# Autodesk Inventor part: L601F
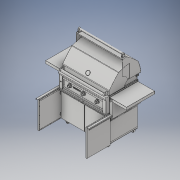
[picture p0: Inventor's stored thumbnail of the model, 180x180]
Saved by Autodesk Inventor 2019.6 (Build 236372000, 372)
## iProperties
Created: 2025-04
Part Number: L601F
Material: Generic
Description: CATIA V5 STEP
Document SubType Name: Modeling
Designer: MMAK
Authority: none
Density: 1 g/cm^3
Appearance: Default
Company: none
Title: C:\Users\MMAK\Documents\SmarTeam\WEBSITE CAD\SEDONA\2025 SEDONA\L601F.stp
Author: none
Revision Number: ANY
Sending System: CATIA V5 STEP AP203 v2
Preprocessor: CATIA Unofficial Packaging Version SP2
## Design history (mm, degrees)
feature "81699-1_81679-1_81678-1_37889-1-solid1"
feature "81699-1_81679-1_81678-1_32769-1-solid1"
feature "81699-1_81679-1_81678-1_32769-2-solid1"
feature "81699-1_81679-1_81678-1_32218--1-solid1"
feature "81699-1_81679-1_81678-1_32218--2-solid1"
feature "81699-1_81679-1_81534-2_37528-2-solid1"
feature "81699-1_81679-1_81534-2_32769-1-solid1"
feature "81699-1_81679-1_81534-2_32769-2-solid1"
feature "81699-1_81679-1_81534-2_32218-14-solid1"
feature "81699-1_81679-1_81534-2_37165-1-solid1"
feature "81699-1_81679-1_81676-2_37886-1-solid1"
feature "81699-1_81679-1_81676-2_32769-1-solid1"
feature "81699-1_81679-1_81676-2_32769-2-solid1"
feature "81699-1_81679-1_81676-2_37165-11-solid1"
feature "81699-1_81679-1_81677-1_37887-1-solid1"
feature "81699-1_81679-1_81677-1_37901-1-solid1"
feature "81699-1_81679-1_81677-1_32769-1-solid1"
feature "81699-1_81679-1_81677-1_32769-2-solid1"
feature "81699-1_81679-1_81677-1_32769-3-solid1"
feature "81699-1_81679-1_81677-1_32769-4-solid1"
feature "81699-1_81679-1_81677-1_32769-5-solid1"
feature "81699-1_81679-1_81677-1_32769-6-solid1"
feature "81699-1_81679-1_81677-1_32769-7-solid1"
feature "81699-1_81679-1_81677-1_32769-8-solid1"
feature "81699-1_81679-1_81677-1_32769-9-solid1"
feature "81699-1_81679-1_81677-1_32769-10-solid1"
feature "81699-1_81679-1_81677-1_32769-11-solid1"
feature "81699-1_81679-1_81677-1_32769-12-solid1"
feature "81699-1_81679-1_81677-1_32769-21-solid1"
feature "81699-1_81679-1_81677-1_32769-25-solid1"
feature "81699-1_81679-1_81677-1_32769-26-solid1"
feature "81699-1_81679-1_81677-1_32769-27-solid1"
feature "81699-1_81679-1_30662-1-solid1"
feature "81699-1_81679-1_30662-1-solid2"
feature "81699-1_81679-1_30662-1-solid3"
feature "81699-1_81679-1_30662-2-solid1"
feature "81699-1_81679-1_30662-2-solid2"
feature "81699-1_81679-1_30662-2-solid3"
feature "81699-1_81679-1_33843-1-solid1"
feature "81699-1_81679-1_33843-1-solid2"
feature "81699-1_81679-1_33843-2-solid1"
feature "81699-1_81679-1_33843-2-solid2"
feature "81699-1_81679-1_37167-1-solid1"
feature "81699-1_81679-1_37167-17-solid1"
feature "81699-1_81679-1_37167-18-solid1"
feature "81699-1_81679-1_37167-19-solid1"
feature "81699-1_81679-1_37167-21-solid1"
feature "81699-1_81679-1_37167-24-solid1"
feature "81699-1_81679-1_37167-26-solid1"
feature "81699-1_81679-1_37167-28-solid1"
feature "81699-1_81679-1_37167-30-solid1"
feature "81699-1_81679-1_37167-32-solid1"
feature "81699-1_81679-1_37167-34-solid1"
feature "81699-1_81679-1_37167-36-solid1"
feature "81699-1_81679-1_37167-38-solid1"
feature "81699-1_81679-1_37167-40-solid1"
feature "81699-1_81679-1_37167-42-solid1"
feature "81699-1_81679-1_37167-44-solid1"
feature "81699-1_81404-3_37070-1-solid1"
feature "81699-1_81404-3_32769-1-solid1"
feature "81699-1_81404-3_32769-2-solid1"
feature "81699-1_81404-3_32769-4-solid1"
feature "81699-1_81404-3_32769-6-solid1"
feature "81699-1_37888-1-solid1"
feature "81699-1_37907-2-solid1"
feature "81699-1_37168-1-solid1"
feature "81699-1_37168-4-solid1"
feature "81699-1_70696-2_37100-1-solid1"
feature "81699-1_70696-2_34888-1-solid1"
feature "81699-1_70696-2_31643-1-solid1"
feature "81699-1_70696-2_31643-3-solid1"
feature "81699-1_70696-1_37100-1-solid1"
feature "81699-1_70696-1_34888-1-solid1"
feature "81699-1_70696-1_31643-1-solid1"
feature "81699-1_70696-1_31643-3-solid1"
feature "81699-1_70696-3_37100-1-solid1"
feature "81699-1_70696-3_31643-2-solid1"
feature "81699-1_70696-3_34888-3-solid1"
feature "81699-1_70696-3_31643-4-solid1"
feature "81699-1_70696-4_37100-1-solid1"
feature "81699-1_70696-4_31643-2-solid1"
feature "81699-1_70696-4_34888-3-solid1"
feature "81699-1_70696-4_31643-4-solid1"
feature "81699-1_31876-10-solid1"
feature "81699-1_31876-1-solid1"
feature "81699-1_31876-2-solid1"
feature "81699-1_31876-5-solid1"
feature "81699-1_31876-11-solid1"
feature "81699-1_31876-12-solid1"
feature "81699-1_37167-47-solid1"
feature "81699-1_37167-45-solid1"
feature "81699-1_37167-48-solid1"
feature "81699-1_37167-46-solid1"
feature "81699-1_37167-41-solid1"
feature "81699-1_37167-43-solid1"
feature "81699-1_37167-49-solid1"
feature "81699-1_37167-50-solid1"
feature "81699-1_37165-3-solid1"
feature "81699-1_37165-2-solid1"
feature "81699-1_30292-1-solid1"
feature "81699-1_30292-2-solid1"
feature "81699-1_30292-4-solid1"
feature "81699-1_30292-6-solid1"
feature "81699-1_30292-7-solid1"
feature "81699-1_81530-1_37102-1-solid1"
feature "81699-1_81530-1_31205-1-solid1"
feature "81699-1_81530-1_31206-5-solid1"
feature "81699-1_81530-1_31206-6-solid1"
feature "81699-1_81530-1_31206-4-solid1"
feature "81699-1_81530-1_31206-7-solid1"
feature "81699-1_37166-2-solid1"
feature "81699-1_37166-1-solid1"
feature "81699-1_37166-3-solid1"
feature "81699-1_37166-4-solid1"
feature "81699-1_37166-6-solid1"
feature "81699-1_37166-10-solid1"
feature "81699-1_37166-12-solid1"
feature "81699-1_37166-15-solid1"
feature "81699-1_81698-1_81703-1_37540-1-solid1"
feature "81699-1_81698-1_81703-1_37797-1-solid1"
feature "81699-1_81698-1_81703-1_37978-1-solid1"
feature "81699-1_81698-1_81703-1_30292-1-solid1"
feature "81699-1_81698-1_81703-1_30292-2-solid1"
feature "81699-1_81698-1_81703-1_30292-3-solid1"
feature "81699-1_81698-1_81703-1_30292-5-solid1"
feature "81699-1_81698-1_81703-1_30292-6-solid1"
feature "81699-1_81698-1_81703-1_30292-7-solid1"
feature "81699-1_81698-1_81703-1_30292-8-solid1"
feature "81699-1_81698-1_81703-1_30292-9-solid1"
feature "81699-1_81698-1_81703-1_30292-10-solid1"
feature "81699-1_81698-1_81703-1_30292-11-solid1"
feature "81699-1_81698-1_81703-1_30292-12-solid1"
feature "81699-1_81698-1_81703-1_30292-13-solid1"
feature "81699-1_81698-1_81703-1_30292-14-solid1"
feature "81699-1_81698-1_81703-1_30292-16-solid1"
feature "81699-1_81698-1_81703-1_30292-18-solid1"
feature "81699-1_81698-1_81703-1_30292-20-solid1"
feature "81699-1_81698-1_81703-1_30292-22-solid1"
feature "81699-1_81698-1_32218--1-solid1"
feature "81699-1_81698-1_32218--2-solid1"
feature "81699-1_81698-1_32218--3-solid1"
feature "81699-1_81698-1_32218--4-solid1"
feature "81699-1_81698-2_81703-1_37540-1-solid1"
feature "81699-1_81698-2_81703-1_37797-1-solid1"
feature "81699-1_81698-2_81703-1_37978-1-solid1"
feature "81699-1_81698-2_81703-1_30292-1-solid1"
feature "81699-1_81698-2_81703-1_30292-2-solid1"
feature "81699-1_81698-2_81703-1_30292-3-solid1"
feature "81699-1_81698-2_81703-1_30292-5-solid1"
feature "81699-1_81698-2_81703-1_30292-6-solid1"
feature "81699-1_81698-2_81703-1_30292-7-solid1"
feature "81699-1_81698-2_81703-1_30292-8-solid1"
feature "81699-1_81698-2_81703-1_30292-9-solid1"
feature "81699-1_81698-2_81703-1_30292-10-solid1"
feature "81699-1_81698-2_81703-1_30292-11-solid1"
feature "81699-1_81698-2_81703-1_30292-12-solid1"
feature "81699-1_81698-2_81703-1_30292-13-solid1"
feature "81699-1_81698-2_81703-1_30292-14-solid1"
feature "81699-1_81698-2_81703-1_30292-16-solid1"
feature "81699-1_81698-2_81703-1_30292-18-solid1"
feature "81699-1_81698-2_81703-1_30292-20-solid1"
feature "81699-1_81698-2_81703-1_30292-22-solid1"
feature "81699-1_81698-2_32218--1-solid1"
feature "81699-1_81698-2_32218--2-solid1"
feature "81699-1_81698-2_32218--3-solid1"
feature "81699-1_81698-2_32218--4-solid1"
feature "81699-1_81697-2_81702-1_37540-1-solid1"
feature "81699-1_81697-2_81702-1_37549-1-solid1"
feature "81699-1_81697-2_81702-1_37978-1-solid1"
feature "81699-1_81697-2_81702-1_30292-1-solid1"
feature "81699-1_81697-2_81702-1_30292-2-solid1"
feature "81699-1_81697-2_81702-1_30292-3-solid1"
feature "81699-1_81697-2_81702-1_30292-4-solid1"
feature "81699-1_81697-2_81702-1_30292-5-solid1"
feature "81699-1_81697-2_81702-1_30292-6-solid1"
feature "81699-1_81697-2_81702-1_30292-7-solid1"
feature "81699-1_81697-2_81702-1_30292-8-solid1"
feature "81699-1_81697-2_81702-1_30292-9-solid1"
feature "81699-1_81697-2_81702-1_30292-10-solid1"
feature "81699-1_81697-2_81702-1_30292-11-solid1"
feature "81699-1_81697-2_81702-1_30292-12-solid1"
feature "81699-1_81697-2_81702-1_30292-13-solid1"
feature "81699-1_81697-2_81702-1_30292-15-solid1"
feature "81699-1_81697-2_81702-1_30292-17-solid1"
feature "81699-1_81697-2_81702-1_30292-19-solid1"
feature "81699-1_81697-2_81702-1_30292-21-solid1"
feature "81699-1_81697-2_32218--1-solid1"
feature "81699-1_81697-2_32218--2-solid1"
feature "81699-1_81697-2_32218--3-solid1"
feature "81699-1_81697-2_32218--4-solid1"
feature "81699-1_81697-3_81702-1_37540-1-solid1"
feature "81699-1_81697-3_81702-1_37549-1-solid1"
feature "81699-1_81697-3_81702-1_37978-1-solid1"
feature "81699-1_81697-3_81702-1_30292-1-solid1"
feature "81699-1_81697-3_81702-1_30292-2-solid1"
feature "81699-1_81697-3_81702-1_30292-3-solid1"
feature "81699-1_81697-3_81702-1_30292-4-solid1"
feature "81699-1_81697-3_81702-1_30292-5-solid1"
feature "81699-1_81697-3_81702-1_30292-6-solid1"
feature "81699-1_81697-3_81702-1_30292-7-solid1"
feature "81699-1_81697-3_81702-1_30292-8-solid1"
feature "81699-1_81697-3_81702-1_30292-9-solid1"
feature "81699-1_81697-3_81702-1_30292-10-solid1"
feature "81699-1_81697-3_81702-1_30292-11-solid1"
feature "81699-1_81697-3_81702-1_30292-12-solid1"
feature "81699-1_81697-3_81702-1_30292-13-solid1"
feature "81699-1_81697-3_81702-1_30292-15-solid1"
feature "81699-1_81697-3_81702-1_30292-17-solid1"
feature "81699-1_81697-3_81702-1_30292-19-solid1"
feature "81699-1_81697-3_81702-1_30292-21-solid1"
feature "81699-1_81697-3_32218--1-solid1"
feature "81699-1_81697-3_32218--2-solid1"
feature "81699-1_81697-3_32218--3-solid1"
feature "81699-1_81697-3_32218--4-solid1"
feature "81699-1_37795-3-solid1"
feature "81699-1_37795-2-solid1"
feature "81699-1_37795-4-solid1"
feature "81699-1_37795-5-solid1"
feature "L601-1_10001-2-solid1"
feature "L601-1_10001-3-solid1"
feature "L601-1_10001-4-solid1"
feature "L601-1_11117-1-solid1"
feature "L601-1_11117-2-solid1"
feature "L601-1_11117-3-solid1"
feature "L601-1_11117-4-solid1"
feature "L601-1_14012-1-solid1"
feature "L601-1_14012-2-solid1"
feature "L601-1_14012-4-solid1"
feature "L601-1_14012-5-solid1"
feature "L601-1_14012-6-solid1"
feature "L601-1_14012-7-solid1"
feature "L601-1_14012-8-solid1"
feature "L601-1_14012-9-solid1"
feature "L601-1_14012-10-solid1"
feature "L601-1_14012-11-solid1"
feature "L601-1_14012-12-solid1"
feature "L601-1_14012-14-solid1"
feature "L601-1_14013-1-solid1"
feature "L601-1_14013-2-solid1"
feature "L601-1_81632-1_34062-1-solid1"
feature "L601-1_81632-1_33767-1-solid1"
feature "L601-1_81632-1_33768-1-solid1"
feature "L601-1_81632-3_34062-1-solid1"
feature "L601-1_81632-3_33767-1-solid1"
feature "L601-1_81632-3_33768-1-solid1"
feature "L601-1_81692-1_81627-1_37834-2-solid1"
feature "L601-1_81692-1_81627-1_32769-1-solid1"
feature "L601-1_81692-1_81627-1_32769-2-solid1"
feature "L601-1_81692-1_81627-1_32769-3-solid1"
feature "L601-1_81692-1_81627-1_32769-4-solid1"
feature "L601-1_81692-1_81627-1_32769-5-solid1"
feature "L601-1_81692-1_81627-1_31782-1-solid1"
feature "L601-1_81692-1_81627-1_32218-3-solid1"
feature "L601-1_81692-1_81627-1_32218-4-solid1"
feature "L601-1_81692-1_81628-1_37837-2-solid1"
feature "L601-1_81692-1_81628-1_32218-3-solid1"
feature "L601-1_81692-1_81628-1_32218-4-solid1"
feature "L601-1_81692-1_81628-1_31782-1-solid1"
feature "L601-1_81692-1_81628-1_32769-1-solid1"
feature "L601-1_81692-1_81628-1_32769-2-solid1"
feature "L601-1_81692-1_81628-1_32769-3-solid1"
feature "L601-1_81692-1_81628-1_32769-4-solid1"
feature "L601-1_81692-1_14012-1-solid1"
feature "L601-1_81692-1_14012-2-solid1"
feature "L601-1_81692-1_14012-4-solid1"
feature "L601-1_81692-1_14012-6-solid1"
feature "L601-1_81692-1_14012-8-solid1"
feature "L601-1_81692-1_14012-10-solid1"
feature "L601-1_81692-1_14012-12-solid1"
feature "L601-1_81692-1_14012-15-solid1"
feature "L601-1_81692-1_14024-1-solid1"
feature "L601-1_81692-1_14024-1-solid2"
feature "L601-1_81692-1_14024-2-solid1"
feature "L601-1_81692-1_14024-2-solid2"
feature "L601-1_81692-1_70790-1_37801-2-solid1"
feature "L601-1_81692-1_70790-1_14011-1-solid1"
feature "L601-1_81700-1_70793-1_L18041-1-solid1"
feature "L601-1_81700-1_70793-1_33763-1-solid1"
feature "L601-1_81700-1_70793-1_37975-1-solid1"
feature "L601-1_81700-1_32218-1-solid1"
feature "L601-1_81700-1_32218-2-solid1"
feature "L601-1_80733-1_80702-1_34073-1-solid1"
feature "L601-1_80733-1_80702-1_34073-1-solid2"
feature "L601-1_80733-1_80702-1_10041-1-solid1"
feature "L601-1_80733-1_80702-1_10041-2-solid1"
feature "L601-1_80733-1_13029-1-solid1"
feature "L601-1_80733-1_34267-1-solid1"
feature "L601-1_80733-1_34268-1-solid1"
feature "L601-1_80733-1_13024-1-solid1"
feature "NONE"
feature "NONE:1"
feature "NONE:2"
feature "L601-1_80733-1_13024-2-solid1"
feature "L601-1_32469-1-solid1"
feature "L601-1_32469-3-solid1"
feature "L601-1_32469-2-solid1"
feature "L601-1_32469-4-solid1"
feature "L601-1_32477-1-solid1"
feature "L601-1_32477-2-solid1"
feature "L601-1_32554-1-solid1"
feature "L601-1_32554-1-solid2"
feature "L601-1_32554-2-solid1"
feature "L601-1_32554-2-solid2"
feature "L601-1_32554-3-solid1"
feature "L601-1_32554-3-solid2"
feature "L601-1_33558-1-solid1"
feature "L601-1_37979-2-solid1"
feature "L601-1_37980-1-solid1"
feature "L601-1_38061-2-solid1"
feature "L601-1_34075-1-solid1"
feature "L601-1_34075-2-solid1"
feature "L601-1_34106-1-solid1"
feature "L601-1_36967-1-solid1"
feature "L601-1_36967-2-solid1"
feature "L601-1_80696-1_34055-1-solid1"
feature "L601-1_80696-1_34053-1-solid1"
feature "L601-1_80696-1_34054-1-solid1"
feature "L601-1_80696-1_14011-25-solid1"
feature "L601-1_80696-1_14011-27-solid1"
feature "L601-1_80696-1_14011-29-solid1"
feature "L601-1_80696-1_14011-30-solid1"
feature "L601-1_80696-1_14011-32-solid1"
feature "L601-1_80696-1_14011-34-solid1"
feature "L601-1_80696-1_30292-1-solid1"
feature "L601-1_80696-1_30292-3-solid1"
feature "L601-1_80696-1_31643-25-solid1"
feature "L601-1_80696-1_31643-53-solid1"
feature "L601-1_80696-1_30616-27-solid1"
feature "L601-1_80696-1_30616-29-solid1"
feature "L601-1_80696-1_30616-31-solid1"
feature "L601-1_80696-1_30616-44-solid1"
feature "L601-1_80696-1_30616-45-solid1"
feature "L601-1_80696-1_30616-46-solid1"
feature "L601-1_80696-1_30616-48-solid1"
feature "L601-1_80696-1_30616-49-solid1"
feature "L601-1_80696-1_30616-51-solid1"
feature "L601-1_80696-1_30616-52-solid1"
feature "L601-1_80696-1_30616-54-solid1"
feature "L601-1_80696-1_30616-55-solid1"
feature "L601-1_80696-1_14034-3-solid1"
feature "L601-1_80696-1_33758-1-solid1"
feature "L601-1_80696-1_33759-1-solid1"
feature "L601-1_80696-1_34056-1-solid1"
feature "L601-1_80696-1_14011-35-solid1"
feature "L601-1_80696-1_14011-36-solid1"
feature "L601-1_80696-1_14011-38-solid1"
feature "L601-1_80696-1_14011-40-solid1"
feature "L601-1_80696-1_14011-42-solid1"
feature "L601-1_80696-1_14011-44-solid1"
feature "L601-1_80696-1_14011-46-solid1"
feature "L601-1_80696-1_14011-49-solid1"
feature "L601-1_80696-1_14011-51-solid1"
feature "L601-1_80696-1_14011-53-solid1"
feature "L601-1_80696-1_14011-55-solid1"
feature "L601-1_80696-1_14011-57-solid1"
feature "L601-1_80696-1_14011-59-solid1"
feature "L601-1_80696-1_14011-61-solid1"
feature "L601-1_80696-1_14011-63-solid1"
feature "L601-1_80696-1_14011-65-solid1"
feature "L601-1_80696-1_32620-1-solid1"
feature "L601-1_80696-1_32620-2-solid1"
feature "L601-1_80696-1_32620-3-solid1"
feature "L601-1_80696-1_32620-4-solid1"
feature "L601-1_80696-1_32620-5-solid1"
feature "L601-1_80696-1_32620-6-solid1"
feature "L601-1_L20016-1-solid1"
feature "L601-1_L20016-2-solid1"
feature "L601-1_L20016-3-solid1"
feature "L601-1_L20016-4-solid1"
feature "L601-1_30417-1-solid1"
feature "L601-1_31773-1-solid1"
feature "L601-1_31773-2-solid1"
feature "L601-1_31773-3-solid1"
feature "L601-1_31930-8-solid1"
feature "L601-1_31930-9-solid1"
feature "L601-1_31930-10-solid1"
feature "L601-1_31930-11-solid1"
feature "L601-1_31930-12-solid1"
feature "L601-1_31930-13-solid1"
feature "L601-1_31930-14-solid1"
feature "L601-1_31930-15-solid1"
feature "L601-1_31930-16-solid1"
feature "L601-1_31930-17-solid1"
feature "L601-1_37846-1-solid1"
feature "L601-1_37845-1-solid1"
feature "L601-1_32470-1-solid1"
feature "L601-1_32470-2-solid1"
body "Solid1"
body "Solid2"
body "Solid3"
body "Solid4"
body "Solid5"
body "Solid6"
body "Solid7"
body "Solid8"
body "Solid9"
body "Solid10"
body "Solid11"
body "Solid12"
body "Solid13"
body "Solid14"
body "Solid15"
body "Solid16"
body "Solid17"
body "Solid18"
body "Solid19"
body "Solid20"
body "Solid21"
body "Solid22"
body "Solid23"
body "Solid24"
body "Solid25"
body "Solid26"
body "Solid27"
body "Solid28"
body "Solid29"
body "Solid30"
body "Solid31"
body "Solid32"
body "Solid33"
body "Solid34"
body "Solid35"
body "Solid36"
body "Solid37"
body "Solid38"
body "Solid39"
body "Solid40"
body "Solid41"
body "Solid42"
body "Solid43"
body "Solid44"
body "Solid45"
body "Solid46"
body "Solid47"
body "Solid48"
body "Solid49"
body "Solid50"
body "Solid51"
body "Solid52"
body "Solid53"
body "Solid54"
body "Solid55"
body "Solid56"
body "Solid57"
body "Solid58"
body "Solid59"
body "Solid60"
body "Solid61"
body "Solid62"
body "Solid63"
body "Solid64"
body "Solid65"
body "Solid66"
body "Solid67"
body "Solid68"
body "Solid69"
body "Solid70"
body "Solid71"
body "Solid72"
body "Solid73"
body "Solid74"
body "Solid75"
body "Solid76"
body "Solid77"
body "Solid78"
body "Solid79"
body "Solid80"
body "Solid81"
body "Solid82"
body "Solid83"
body "Solid84"
body "Solid85"
body "Solid86"
body "Solid87"
body "Solid88"
body "Solid89"
body "Solid90"
body "Solid91"
body "Solid92"
body "Solid93"
body "Solid94"
body "Solid95"
body "Solid96"
body "Solid97"
body "Solid98"
body "Solid99"
body "Solid100"
body "Solid101"
body "Solid102"
body "Solid103"
body "Solid104"
body "Solid105"
body "Solid106"
body "Solid107"
body "Solid108"
body "Solid109"
body "Solid110"
body "Solid111"
body "Solid112"
body "Solid113"
body "Solid114"
body "Solid115"
body "Solid116"
body "Solid117"
body "Solid118"
body "Solid119"
body "Solid120"
body "Solid121"
body "Solid122"
body "Solid123"
body "Solid124"
body "Solid125"
body "Solid126"
body "Solid127"
body "Solid128"
body "Solid129"
body "Solid130"
body "Solid131"
body "Solid132"
body "Solid133"
body "Solid134"
body "Solid135"
body "Solid136"
body "Solid137"
body "Solid138"
body "Solid139"
body "Solid140"
body "Solid141"
body "Solid142"
body "Solid143"
body "Solid144"
body "Solid145"
body "Solid146"
body "Solid147"
body "Solid148"
body "Solid149"
body "Solid150"
body "Solid151"
body "Solid152"
body "Solid153"
body "Solid154"
body "Solid155"
body "Solid156"
body "Solid157"
body "Solid158"
body "Solid159"
body "Solid160"
body "Solid161"
body "Solid162"
body "Solid163"
body "Solid164"
body "Solid165"
body "Solid166"
body "Solid167"
body "Solid168"
body "Solid169"
body "Solid170"
body "Solid171"
body "Solid172"
body "Solid173"
body "Solid174"
body "Solid175"
body "Solid176"
body "Solid177"
body "Solid178"
body "Solid179"
body "Solid180"
body "Solid181"
body "Solid182"
body "Solid183"
body "Solid184"
body "Solid185"
body "Solid186"
body "Solid187"
body "Solid188"
body "Solid189"
body "Solid190"
body "Solid191"
body "Solid192"
body "Solid193"
body "Solid194"
body "Solid195"
body "Solid196"
body "Solid197"
body "Solid198"
body "Solid199"
body "Solid200"
body "Solid201"
body "Solid202"
body "Solid203"
body "Solid204"
body "Solid205"
body "Solid206"
body "Solid207"
body "Solid208"
body "Solid209"
body "Solid210"
body "Solid211"
body "Solid212"
body "Solid213"
body "Solid214"
body "Solid215"
body "Solid216"
body "Solid217"
body "Solid218"
body "Solid219"
body "Solid220"
body "Solid221"
body "Solid222"
body "Solid223"
body "Solid224"
body "Solid225"
body "Solid226"
body "Solid227"
body "Solid228"
body "Solid229"
body "Solid230"
body "Solid231"
body "Solid232"
body "Solid233"
body "Solid234"
body "Solid235"
body "Solid236"
body "Solid237"
body "Solid238"
body "Solid239"
body "Solid240"
body "Solid241"
body "Solid242"
body "Solid243"
body "Solid244"
body "Solid245"
body "Solid246"
body "Solid247"
body "Solid248"
body "Solid249"
body "Solid250"
body "Solid251"
body "Solid252"
body "Solid253"
body "Solid254"
body "Solid255"
body "Solid256"
body "Solid257"
body "Solid258"
body "Solid259"
body "Solid260"
body "Solid261"
body "Solid262"
body "Solid263"
body "Solid264"
body "Solid265"
body "Solid266"
body "Solid267"
body "Solid268"
body "Solid269"
body "Solid270"
body "Solid271"
body "Solid272"
body "Solid273"
body "Solid274"
body "Solid275"
body "Solid276"
body "Solid277"
body "Solid278"
body "Solid279"
body "Solid280"
body "Solid281"
body "Solid282"
body "Solid283"
body "Solid284"
body "Solid285"
body "Solid286"
body "Solid287"
body "Solid288"
body "Solid289"
body "Solid290"
body "Solid291"
body "Solid292"
body "Solid293"
body "Solid294"
body "Solid295"
body "Solid296"
body "Solid297"
body "Solid298"
body "Solid299"
body "Solid300"
body "Solid301"
body "Solid302"
body "Solid303"
body "Solid304"
body "Solid305"
body "Solid306"
body "Solid307"
body "Solid308"
body "Solid309"
body "Solid310"
body "Solid311"
body "Solid312"
body "Solid313"
body "Solid314"
body "Solid315"
body "Solid316"
body "Solid317"
body "Solid318"
body "Solid319"
body "Solid320"
body "Solid321"
body "Solid322"
body "Solid323"
body "Solid324"
body "Solid325"
body "Solid326"
body "Solid327"
body "Solid328"
body "Solid329"
body "Solid330"
body "Solid331"
body "Solid332"
body "Solid333"
body "Solid334"
body "Solid335"
body "Solid336"
body "Solid337"
body "Solid338"
body "Solid339"
body "Solid340"
body "Solid341"
body "Solid342"
body "Solid343"
body "Solid344"
body "Solid345"
body "Solid346"
body "Solid347"
body "Solid348"
body "Solid349"
body "Solid350"
body "Solid351"
body "Solid352"
body "Solid353"
body "Solid354"
body "Solid355"
body "Solid356"
body "Solid357"
body "Solid358"
body "Solid359"
body "Solid360"
body "Solid361"
body "Solid362"
body "Solid363"
body "Solid364"
body "Solid365"
body "Solid366"
body "Solid367"
body "Solid368"
body "Solid369"
body "Solid370"
body "Solid371"
body "Solid372"
body "Solid373"
body "Solid374"
body "Solid375"
body "Solid376"
body "Solid377"
body "Solid378"
body "Solid379"
body "Solid380"
body "Solid381"
body "Solid382"
body "Solid383"
body "Solid384"
body "Solid385"
body "Solid386"
body "Solid387"
body "Solid388"
body "Solid389"
body "Solid390"
body "Solid391"
body "Solid392"
body "Solid393"
body "Solid394"
body "Solid395"
body "Solid396"
body "Solid397"
body "Solid398"
body "Solid399"
